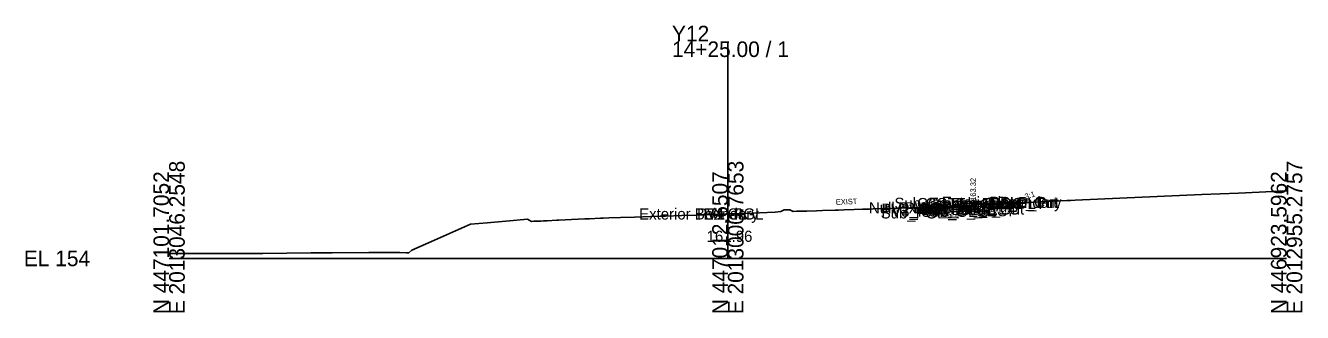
# Model space of a CAD drawing. Extents: x -26 to 1203, y -10 to 9542.
# Drawn here: x -25.7 to 202.8, y 8490.3 to 8541.7 of the extents above; entities that cross this region are included whole.
import ezdxf

# ---------------------------------------------------------------- set-up
doc = ezdxf.new("R2010")
doc.units = 0
for name, color, linetype in [('Default', 7, 'Continuous'), ('Exist Cross Section Cell', 7, 'Continuous'), ('Exist XS Center Line Elevation Label', 7, 'Continuous'), ('Exist XS Ground Line', 7, 'Continuous'), ('Prop CMT Conc Surface', 7, 'Continuous'), ('Prop CMT Concrete Structures', 7, 'Continuous'), ('Prop CMT Pvmt Course 1', 7, 'Continuous'), ('Prop CMT Pvmt Course 1 CG', 7, 'Continuous'), ('Prop CMT Pvmt Course 2', 7, 'Continuous'), ('Prop CMT Pvmt Course 3', 7, 'Continuous'), ('Prop CMT Pvmt Surface', 7, 'Continuous'), ('Prop CMT Slope Grass', 7, 'Continuous'), ('Prop CMT Subgrade Earthwork', 7, 'Continuous'), ('Prop XS Earthwork Shape', 7, 'Continuous'), ('Prop XS Hydro Elevations', 7, 'Continuous'), ('Prop XS SE Text', 7, 'Continuous'), ('Prop XS Side Slope Text', 7, 'Continuous'), ('Scratch_Level_0', 7, 'Continuous')]:
    doc.layers.add(name, color=color, linetype=linetype)

msp = doc.modelspace()

# ---------------------------------------------------------------- linework, layer by layer
at = {"layer": 'Exist Cross Section Cell'}
for p, q in [((100, 8500), (100, 8538.87)), ((0, 8500), (100, 8500)), ((100, 8500), (200, 8500))]:
    msp.add_line(p, q, dxfattribs=at)
at = {"layer": 'Exist XS Ground Line'}
msp.add_lwpolyline([(0, 8500.86), (1.19, 8500.86), (11.66, 8500.85), (14.26, 8500.85), (15.11, 8500.87), (16.75, 8500.88), (25.39, 8501), (26.26, 8501), (27.43, 8501), (29.17, 8501), (35.74, 8501.03), (37.73, 8501.05), (40.82, 8501.08), (41.27, 8501.08), (42.48, 8501.01), (42.89, 8500.99), (43.42, 8501.49), (46.45, 8502.77), (53.93, 8506.1), (56.95, 8506.35), (60.29, 8506.67), (64.15, 8507.05), (64.46, 8506.86), (64.85, 8506.62), (65.26, 8506.64), (66.54, 8506.68), (67.02, 8506.7), (67.65, 8506.74), (69.4, 8506.82), (69.74, 8506.84), (72.02, 8506.95), (74.42, 8507.07), (75.24, 8507.11), (77.19, 8507.19), (77.69, 8507.21), (78.72, 8507.24), (80.77, 8507.31), (83.27, 8507.39), (86.21, 8507.48), (87.86, 8507.54), (88.87, 8507.57), (91.74, 8507.67), (94.47, 8507.77), (97.34, 8507.88), (98.51, 8507.91), (100.09, 8507.96), (102.87, 8508.06), (104.68, 8508.12), (105.68, 8508.15), (108.44, 8508.26), (109.5, 8508.39), (110.1, 8508.69), (110.44, 8508.67), (111.1, 8508.67), (111.7, 8508.37), (112.36, 8508.45), (113.78, 8508.47), (114.16, 8508.48), (115.87, 8508.54), (116.95, 8508.57), (119.23, 8508.64), (119.78, 8508.66), (120.82, 8508.69), (122.61, 8508.75), (124.12, 8508.79), (124.73, 8508.81), (125.34, 8508.83), (126, 8508.85), (128.16, 8508.91), (130.17, 8508.96), (130.94, 8508.98), (132.55, 8509.03), (133.25, 8509.05), (133.56, 8509.06), (134.92, 8509.08), (135.36, 8509.09), (136.35, 8509.18), (138.53, 8509.38), (140, 8509.41), (147.78, 8509.69), (148.72, 8509.77), (160.66, 8510.36), (161.37, 8510.39), (162.15, 8510.43), (184.82, 8511.43), (191.41, 8511.7), (200, 8512.12)], dxfattribs=at)
at = {"layer": 'Prop CMT Conc Surface'}
msp.add_lwpolyline([(141.9, 8509.34), (143.9, 8509.32), (143.9, 8509.82), (144.4, 8509.82)], dxfattribs=at)
at = {"layer": 'Prop CMT Concrete Structures'}
for points in [[(141.9, 8509.34), (143.9, 8509.32), (143.9, 8509.82), (144.4, 8509.82)], [(144.4, 8509.82), (144.4, 8508.84), (141.9, 8508.75)], [(141.9, 8508.75), (141.9, 8509.34)]]:
    msp.add_lwpolyline(points, dxfattribs=at)
at = {"layer": 'Prop CMT Pvmt Course 1'}
for points in [[(133.55, 8509.06), (141.9, 8509.34)], [(141.9, 8509.09), (133.55, 8508.81)], [(133.55, 8509.06), (133.55, 8509.06)], [(133.55, 8508.81), (133.55, 8509.06)], [(141.9, 8509.34), (141.9, 8509.09)], [(99.99, 8507.96), (99.99, 8507.96)]]:
    msp.add_lwpolyline(points, dxfattribs=at)
at = {"layer": 'Prop CMT Pvmt Course 1 CG'}
for points in [[(141.9, 8508.75), (144.9, 8508.85), (145.23, 8508.53)], [(141.9, 8508.42), (141.9, 8508.75)], [(145.23, 8508.53), (141.9, 8508.42)]]:
    msp.add_lwpolyline(points, dxfattribs=at)
at = {"layer": 'Prop CMT Pvmt Course 2'}
for points in [[(133.55, 8508.81), (141.9, 8509.09)], [(133.55, 8508.48), (133.55, 8508.81)], [(141.9, 8508.75), (133.55, 8508.48)], [(141.9, 8509.09), (141.9, 8508.75)]]:
    msp.add_lwpolyline(points, dxfattribs=at)
at = {"layer": 'Prop CMT Pvmt Course 3'}
for points in [[(133.55, 8508.48), (141.9, 8508.75)], [(133.55, 8508.15), (133.55, 8508.48)], [(141.9, 8508.42), (133.55, 8508.15)], [(141.9, 8508.75), (141.9, 8508.42)]]:
    msp.add_lwpolyline(points, dxfattribs=at)
at = {"layer": 'Prop CMT Pvmt Surface'}
msp.add_lwpolyline([(133.55, 8509.06), (141.9, 8509.34)], dxfattribs=at)
at = {"layer": 'Prop CMT Slope Grass'}
msp.add_lwpolyline([(144.4, 8509.82), (153.9, 8510.01), (153.94, 8510.02)], dxfattribs=at)
at = {"layer": 'Prop CMT Subgrade Earthwork'}
for points in [[(133.55, 8508.15), (133.55, 8509.06)], [(133.55, 8508.15), (141.9, 8508.42)], [(141.9, 8508.42), (133.55, 8508.15)], [(141.9, 8508.42), (145.23, 8508.53), (146.56, 8509.87)]]:
    msp.add_lwpolyline(points, dxfattribs=at)
at = {"layer": 'Prop XS Earthwork Shape'}
for points in [[(144.4, 8509.57), (146.33, 8509.63), (145.23, 8508.53), (141.9, 8508.42), (133.55, 8508.15), (133.55, 8509.06), (134.92, 8509.08), (135.36, 8509.09), (135.89, 8509.14), (141.9, 8509.34), (141.9, 8508.75), (144.4, 8508.84)], [(140, 8509.41), (143.9, 8509.55), (143.9, 8509.32), (141.9, 8509.34), (135.89, 8509.14), (136.35, 8509.18), (138.53, 8509.38)], [(144.4, 8509.57), (144.4, 8508.84), (141.9, 8508.75), (141.9, 8509.34), (143.9, 8509.32), (143.9, 8509.55)], [(148.72, 8509.77), (153.59, 8510.01), (146.56, 8509.87), (146.33, 8509.63), (147.78, 8509.69)], [(153.59, 8510.01), (153.9, 8510.01), (153.94, 8510.02)]]:
    msp.add_lwpolyline(points, close=True, dxfattribs=at)

# ---------------------------------------------------------------- texts
at = {"layer": 'Default'}
msp.add_text('-', height=0.0001, dxfattribs=at).set_placement((0, 8500))
at = {"layer": 'Exist Cross Section Cell'}
for s, p in [('Y12', (90, 8538.87)), ('14+25.00 / 1', (90, 8536.07)), ('EL 154', (-26, 8498.6))]:
    msp.add_text(s, height=2.8, dxfattribs=at).set_placement(p)
for s, p in [('N 447101.7052', (0, 8490)), ('E 2013046.2548', (2.8, 8490)), ('N 447012.6507', (100, 8490)), ('E 2013000.7653', (102.8, 8490)), ('N 446923.5962', (200, 8490)), ('E 2012955.2757', (202.8, 8490))]:
    msp.add_text(s, height=2.8, rotation=90, dxfattribs=at).set_placement(p)
at = {"layer": 'Exist XS Center Line Elevation Label'}
msp.add_text('161.96', height=2, dxfattribs=at).set_placement((96.21, 8502.96))
at = {"layer": 'Prop XS Hydro Elevations'}
msp.add_text('163.32', height=1, rotation=90, dxfattribs=at).set_placement((144.4, 8510.32))
at = {"layer": 'Prop XS SE Text'}
msp.add_text('EXIST', height=1, rotation=1.8856, dxfattribs=at).set_placement((119.34, 8509.6))
at = {"layer": 'Prop XS Side Slope Text'}
msp.add_text('3:1', height=1, rotation=18.4349, dxfattribs=at).set_placement((153.32, 8510.55))
at = {"layer": 'Scratch_Level_0'}
for s, p in [('Sub_Trench_Out_DLT', (129.82, 8508.87)), ('CG_Top_Face', (133.86, 8508.82)), ('CG_Top_BOC', (135.38, 8508.82)), ('Exterior Boundary', (138.31, 8509.04)), ('Slope_Cut', (146.5, 8509.04)), ('CSLP_Pnt', (146.77, 8509.01)), ('Exterior Boundary', (84.13, 8506.96)), ('PV1_PGL', (94.47, 8506.96)), ('EX CL', (95.66, 8506.96)), ('Null Ex EOP', (125.25, 8508.06)), ('Sub_PGL', (127.36, 8507.15)), ('PV2_PGL', (127.46, 8507.81)), ('PV3_PGL', (127.46, 8507.48)), ('PV1', (131.63, 8508.06)), ('CG1_Shelf_Out', (134.15, 8507.85)), ('CG_Bot_IE', (134.51, 8507.75)), ('Sub_OEOT', (134.67, 8507.42)), ('CG_Top_Gut', (134.83, 8508.32)), ('PV2_OEOT', (134.77, 8508.09)), ('PV3_OEOT', (134.77, 8507.75)), ('CG_Bot_BOC', (135.41, 8507.84)), ('PV1_OEOT', (135.34, 8508.34)), ('Sub_OEOP', (138.03, 8507.53))]:
    msp.add_text(s, height=2, dxfattribs=at).set_placement(p)

doc.saveas('drawing.dxf')
